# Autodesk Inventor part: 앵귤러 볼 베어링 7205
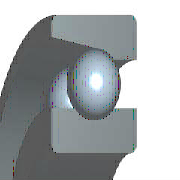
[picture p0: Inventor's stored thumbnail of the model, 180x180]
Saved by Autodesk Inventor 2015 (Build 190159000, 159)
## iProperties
Created: 2012-02
Part Number: 앵귤러 볼 베어링 7205
Material: 강철, 연강
Description: 앵귤러 콘택트 볼 베어링
Document SubType Name: Modeling
Standard: KS B 2024
Designer: mduedu
Standards Organization: KS
Language: ko-KR
Size Designation: 7205 - 25 x 52 x 15
Categories: <MemberInstance><Categories><Category DisplayName="샤프트 부품" InternalName="7f7aeb1f-a693-4053-b835-cee3144e0d98" Mnemonic="SHFT"><Category DisplayName="베어링" Inter
Density: 1 g/cm^3
Appearance: 노란색
IsCustomPart: 1
Author: mduedu
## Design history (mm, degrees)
sketch "스케치" dims "d1" = 7.02 (= -0.26 x WD + 0.26 x BD)
  geometry: L1 (3.99, 19.25)-(11.01, 19.25); L2 (7.5, 22.76)-(7.5, 15.74); L3 (0, 16.901)-(4.892, 16.901); L4 (0, 12.5)-(15, 12.5); L5 (8.11, 22.707)-(0, 24.137); L6 (15, 16.901)-(15, 12.5); L7 (15, 16.901)-(10.108, 16.901); L8 (15, 21.599)-(10.108, 21.599); L9 (15, 21.599)-(15, 26); L10 (0, 26)-(15, 26); L11 (-2.4, 0)-(14.4, 0) reference; L12 (0, -1.44)-(0, 8.99) reference; 1 further point
  constraints: 20 end point, 4 point on line, 3 symmetric about line, 2 midpoint, 2 parallel, 1 perpendicular, 14 other
  dimensions: "d0" = 10 deg angle of L8 L5; "d11" = 25 diameter of L4 L11 (= WD); "d12" = 52 diameter of L10 L11 (= BD); "d13" = 15 distance between parallel lines of L6 L12 (= KB); "d14" = 33.802 diameter of L7 L11 (= 0.326 x BD + 0.674 x WD)
revolve "본체" stored, may be unused: angle "d6" = 90 deg
revolve "볼" stored, may be unused: angle "d8" = 90 deg
pattern_circular "IDS_ARRAYBALL[SIMPL:T]" dims angle "d4" = 360 deg
body "Solid1"
fillet "모깎기1" dims "d2" = 1 (= KRS)
other parameters: "WD" = 25 [user parameter; used in 5 equation terms], "BD" = 52 [user parameter; used in 5 equation terms], "KB" = 15 [user parameter; used in 1 equation term], "KRS" = 1 [user parameter; used in 1 equation term], "d5" = 0, "d7" = 0, "d9" = 0, "d15" = 0, "d16" = 0, "BC0" = 1.02e+07 [user parameter], "BBA" = 30 deg [user parameter], "BC" = 1.56e+07 [user parameter], "KR1S" = 0.6 [user parameter], "BR" = 26 (= 0.5 x BD) [user parameter], "WR" = 12.5 (= 0.5 x WD) [user parameter]
